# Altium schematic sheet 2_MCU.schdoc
size 307 x 218 mm; Symbol: Artery_A4; Device: Artery_A4; Company: Artery Technology; Drawed: SD; Version: 1.0; Page Size: A4; @Project Name: AT-START-F456; @Page Count: 4; @Update Date: 2025-01-20; @Create Date: 2024-11-08; @Schematic Name: AT-START-F456 V1.0; @Page No: 2; @Page Name: MCU; @Board Name: AT-START-F456_V1.0; @Create Time: 17:57:27; @Update Time: 15:09:47; Width: 1171; Height: 826; Region Start: 1; X Region Count: 1; Y Region Count: 1; Title Block Position: 3
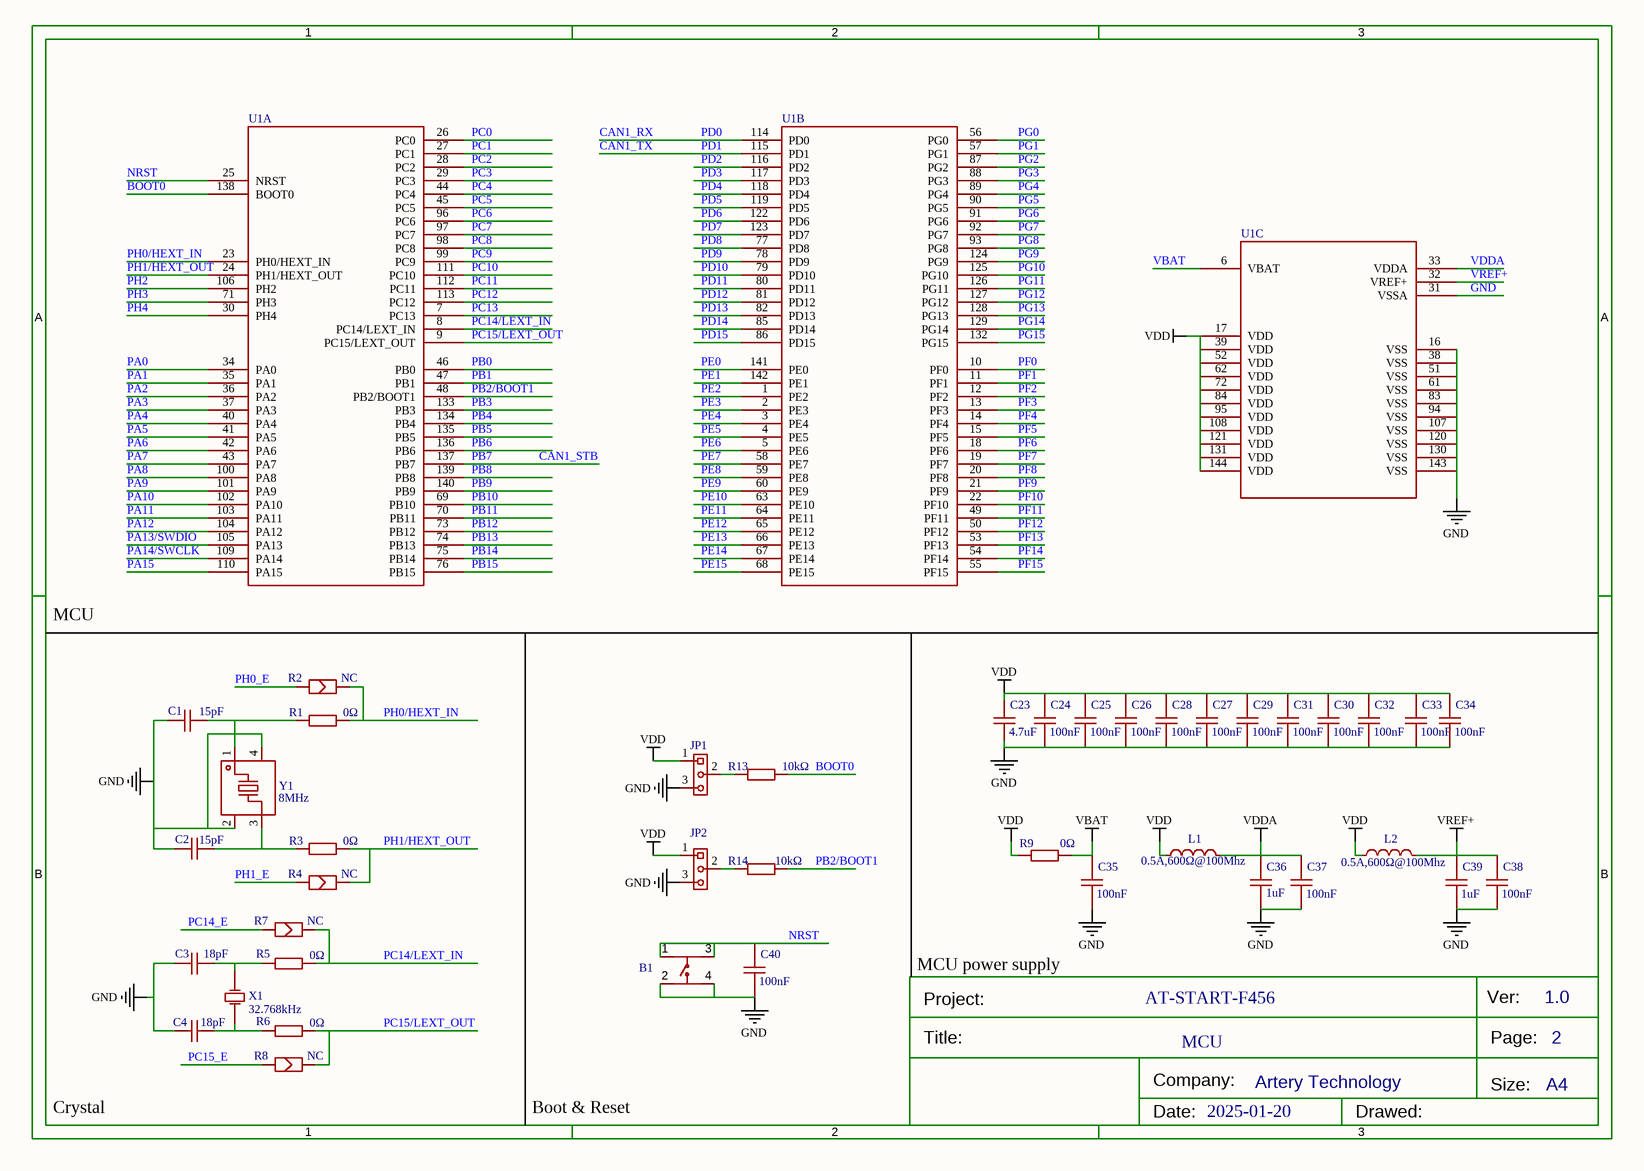
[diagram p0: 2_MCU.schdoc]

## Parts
B1  贴片按键6*6*5 黑色  [SW-SMD_4P-L6.0-W6.0-P4.50-LS9.0]  (value not drawn)
C1  15pF  [C0603]
C2  15pF  [C0603]
C3  18pF  [C0603]
C4  18pF  [C0603]
C23  4.7uF  [C0603]
C24  100nF  [C0603]
C25  100nF  [C0603]
C26  100nF  [C0603]
C27  100nF  [C0603]
C28  100nF  [C0603]
C29  100nF  [C0603]
C30  100nF  [C0603]
C31  100nF  [C0603]
C32  100nF  [C0603]
C33  100nF  [C0603]
C34  100nF  [C0603]
C35  100nF  [C0603]
C36  1uF  [C0603]
C37  100nF  [C0603]
C38  100nF  [C0603]
C39  1uF  [C0603]
C40  100nF  [C0603]
JP1  Jumper 1x3P  [HEADER 1X3]  (value not drawn)
JP2  Jumper 1x3P  [HEADER 1X3]  (value not drawn)
L1  0.5A,600Ω@100Mhz  [0603_L]
L2  0.5A,600Ω@100Mhz  [0603_L]
R1  0Ω  [R0603]
R2  NC  [SB-PAD]
R3  0Ω  [R0603]
R4  NC  [SB-PAD]
R5  0Ω  [R0603]
R6  0Ω  [R0603]
R7  NC  [SB-PAD]
R8  NC  [SB-PAD]
R9  0Ω  [R0603]
R13  10kΩ  [R0603]
R14  10kΩ  [R0603]
U1  AT32F457ZET7  [LQFP144_20*20]  (value not drawn)  (parts A,B,C of 3)
X1  32.768kHz  [OSC-TH_BD2.0-P0.70-D0.3]
Y1  8MHz  [CRYSTAL-SMD_4P-L3.2-W2.5-BL]

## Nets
GND: B1.2 B1.4 C1.1 C2.1 C3.1 C4.1 C23.2 C24.2 C25.2 C26.2 C27.2 C28.2 C29.2 C30.2 C31.2 C32.2 C33.2 C34.2 C35.2 C36.2 C37.2 C38.2 C39.2 C40.2 JP1.3 JP2.3 U1.16(VSS) U1.31(VSSA) U1.38(VSS) U1.51(VSS) U1.61(VSS) U1.83(VSS) U1.94(VSS) U1.107(VSS) U1.120(VSS) U1.130(VSS) U1.143(VSS) Y1.2(GND) Y1.4(GND)
VBAT: C35.1 R9.1 U1.6(VBAT)
VDD: C23.1 C24.1 C25.1 C26.1 C27.1 C28.1 C29.1 C30.1 C31.1 C32.1 C33.1 C34.1 JP1.1 JP2.1 L1.1 L2.1 R9.2 U1.17(VDD) U1.39(VDD) U1.52(VDD) U1.62(VDD) U1.72(VDD) U1.84(VDD) U1.95(VDD) U1.108(VDD) U1.121(VDD) U1.131(VDD) U1.144(VDD)
VDDA: C36.1 C37.1 L1.2 U1.33(VDDA)
VREF+: C38.1 C39.1 L2.2 U1.32(VREF+)
BOOT0: R13.2 U1.138(BOOT0)
CAN1_RX: U1.114(PD0)  [also labelled PD0]
CAN1_STB: U1.137(PB7)  [also labelled PB7]
CAN1_TX: U1.115(PD1)  [also labelled PD1]
NRST: B1.1 B1.3 C40.1 U1.25(NRST)
PA0: U1.34(PA0)
PA1: U1.35(PA1)
PA2: U1.36(PA2)
PA3: U1.37(PA3)
PA4: U1.40(PA4)
PA5: U1.41(PA5)
PA6: U1.42(PA6)
PA7: U1.43(PA7)
PA8: U1.100(PA8)
PA9: U1.101(PA9)
PA10: U1.102(PA10)
PA11: U1.103(PA11)
PA12: U1.104(PA12)
PA13/SWDIO: U1.105(PA13)
PA14/SWCLK: U1.109(PA14)
PA15: U1.110(PA15)
PB0: U1.46(PB0)
PB1: U1.47(PB1)
PB2/BOOT1: R14.2 U1.48(PB2/BOOT1)
PB3: U1.133(PB3)
PB4: U1.134(PB4)
PB5: U1.135(PB5)
PB6: U1.136(PB6)
PB8: U1.139(PB8)
PB9: U1.140(PB9)
PB10: U1.69(PB10)
PB11: U1.70(PB11)
PB12: U1.73(PB12)
PB13: U1.74(PB13)
PB14: U1.75(PB14)
PB15: U1.76(PB15)
PC0: U1.26(PC0)
PC1: U1.27(PC1)
PC2: U1.28(PC2)
PC3: U1.29(PC3)
PC4: U1.44(PC4)
PC5: U1.45(PC5)
PC6: U1.96(PC6)
PC7: U1.97(PC7)
PC8: U1.98(PC8)
PC9: U1.99(PC9)
PC10: U1.111(PC10)
PC11: U1.112(PC11)
PC12: U1.113(PC12)
PC13: U1.7(PC13)
PC14/LEXT_IN: R5.2 R7.2 U1.8(PC14/LEXT_IN)
PC14_E: R7.1
PC15/LEXT_OUT: R6.2 R8.2 U1.9(PC15/LEXT_OUT)
PC15_E: R8.1
PD2: U1.116(PD2)
PD3: U1.117(PD3)
PD4: U1.118(PD4)
PD5: U1.119(PD5)
PD6: U1.122(PD6)
PD7: U1.123(PD7)
PD8: U1.77(PD8)
PD9: U1.78(PD9)
PD10: U1.79(PD10)
PD11: U1.80(PD11)
PD12: U1.81(PD12)
PD13: U1.82(PD13)
PD14: U1.85(PD14)
PD15: U1.86(PD15)
PE0: U1.141(PE0)
PE1: U1.142(PE1)
PE2: U1.1(PE2)
PE3: U1.2(PE3)
PE4: U1.3(PE4)
PE5: U1.4(PE5)
PE6: U1.5(PE6)
PE7: U1.58(PE7)
PE8: U1.59(PE8)
PE9: U1.60(PE9)
PE10: U1.63(PE10)
PE11: U1.64(PE11)
PE12: U1.65(PE12)
PE13: U1.66(PE13)
PE14: U1.67(PE14)
PE15: U1.68(PE15)
PF0: U1.10(PF0)
PF1: U1.11(PF1)
PF2: U1.12(PF2)
PF3: U1.13(PF3)
PF4: U1.14(PF4)
PF5: U1.15(PF5)
PF6: U1.18(PF6)
PF7: U1.19(PF7)
PF8: U1.20(PF8)
PF9: U1.21(PF9)
PF10: U1.22(PF10)
PF11: U1.49(PF11)
PF12: U1.50(PF12)
PF13: U1.53(PF13)
PF14: U1.54(PF14)
PF15: U1.55(PF15)
PG0: U1.56(PG0)
PG1: U1.57(PG1)
PG2: U1.87(PG2)
PG3: U1.88(PG3)
PG4: U1.89(PG4)
PG5: U1.90(PG5)
PG6: U1.91(PG6)
PG7: U1.92(PG7)
PG8: U1.93(PG8)
PG9: U1.124(PG9)
PG10: U1.125(PG10)
PG11: U1.126(PG11)
PG12: U1.127(PG12)
PG13: U1.128(PG13)
PG14: U1.129(PG14)
PG15: U1.132(PG15)
PH0/HEXT_IN: R1.2 R2.2 U1.23(PH0/HEXT_IN)
PH0_E: R2.1
PH1/HEXT_OUT: R3.2 R4.2 U1.24(PH1/HEXT_OUT)
PH1_E: R4.1
PH2: U1.106(PH2)
PH3: U1.71(PH3)
PH4: U1.30(PH4)
NetC1_2: C1.2 R1.1 Y1.1
NetC2_2: C2.2 R3.1 Y1.3
NetC3_2: C3.2 R5.1 X1.1(OSC1)
NetC4_2: C4.2 R6.1 X1.2(OSC2)
NetJP1_2: JP1.2 R13.1
NetJP2_2: JP2.2 R14.1

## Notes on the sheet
- MCU
- MCU power supply
- AT-START-F456
- Crystal
- Boot & Reset
- 2025-01-20

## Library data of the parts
B1 = K2-1102SP-C3SC-04: Manufacturer: Korean Hroparts Elec; Paste Type: expand; Convert to PCB: yes
C1 C2 = CL10C150JB8NNNC: Manufacturer: SAMSUNG(三星); Add into BOM: yes; Tolerance: ±5%; Voltage Rated: 50V; Temperature Coefficient: C0G; Origin Footprint: 0603_C-M
C3 C4 = CL10C180JB8NNNC: Manufacturer: SAMSUNG(三星); Add into BOM: yes; Tolerance: ±5%; Voltage Rated: 50V; Temperature Coefficient: C0G; Origin Footprint: 0603_C-M
C23 = CL10A475KO8NNNC: Manufacturer: SAMSUNG(三星); Add into BOM: yes; Tolerance: ±10%; Voltage Rated: 16V; Temperature Coefficient: X5R; Origin Footprint: 0603_C-M
C24-C35 C37 C38 C40 = CC0603KRX7R9BB104: Manufacturer: YAGEO(国巨); Add into BOM: yes; Tolerance: ±10%; Voltage Rated: 50V; Temperature Coefficient: X7R; Origin Footprint: 0603_C-M
C36 C39 = CL10A105KB8NNNC: Manufacturer: SAMSUNG(三星); Add into BOM: yes; Tolerance: ±10%; Voltage Rated: 50V; Temperature Coefficient: X5R; Origin Footprint: 0603_C-M
JP1 JP2 = Jumper 1x3P: Convert to PCB: yes
L1 L2 = 0.5A,600Ω@100Mhz: Convert to PCB: yes
R1 R3 R5 R6 R9 = 0603WAF0000T5E: Manufacturer: UNI-ROYAL(厚声); Add into BOM: yes; Tolerance: ±1%; Power(Watts): 100mW; Overload Voltage (Max): 75V
R2 R4 R7 R8 = NC: Convert to PCB: yes
R13 R14 = 0603WAF1002T5E: Manufacturer: UNI-ROYAL(厚声); Add into BOM: yes; Tolerance: ±1%; Power(Watts): 100mW; Temperature Coefficient: ±100ppm/℃; Overload Voltage (Max): 75V
U1 = AT32F457ZET7: Convert to PCB: yes; Relevance: []
X1 = X206032768KGB2SC: Manufacturer: YXC(扬兴晶振); Add into BOM: yes; Crystal Type: 直插晶振; Normal temperature Frequency Tolerance: ±10ppm; Load Capacitor: 12.5pF
Y1 = CJ13-080001210B20: Manufacturer: CJ(江苏长电/长晶); Add into BOM: yes; Normal temperature Frequency Tolerance: ±10ppm; External load capacitor: 12pF; Paste Type: recommend; Origin Footprint: OSC-SMD_4P-L5.0-W3.2-BL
